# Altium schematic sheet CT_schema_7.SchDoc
size 370 x 335 mm
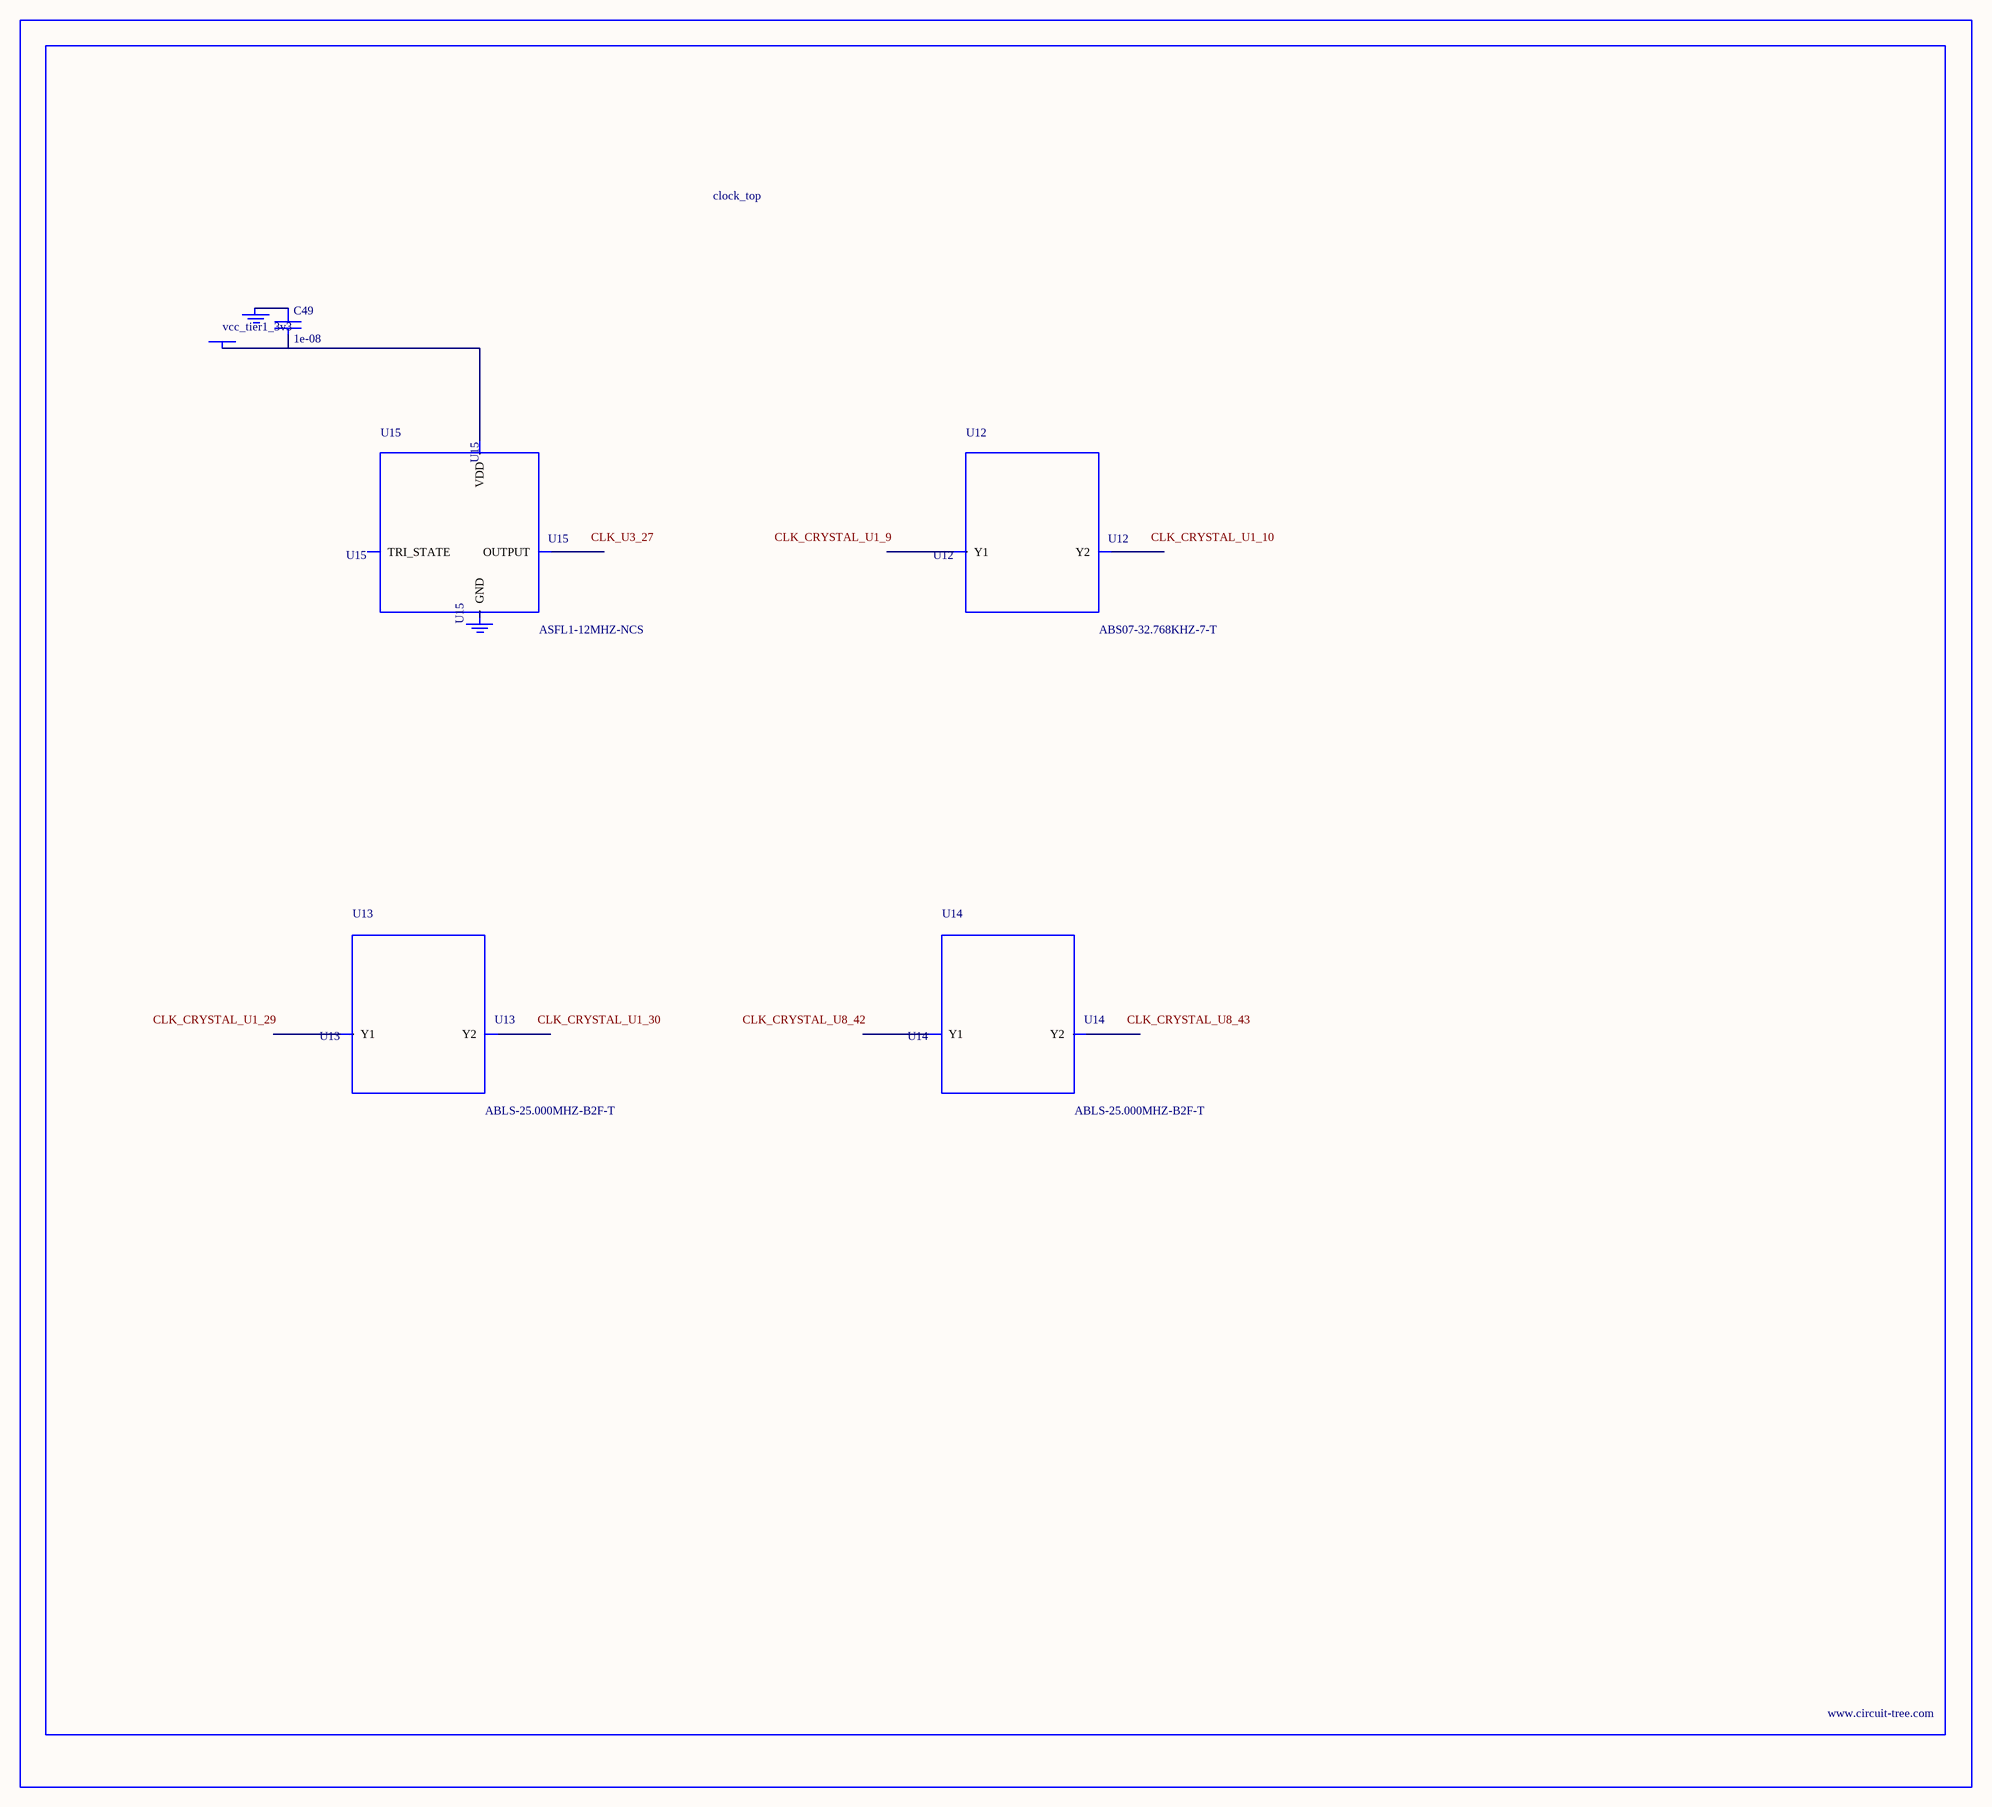
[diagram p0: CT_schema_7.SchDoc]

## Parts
BORDER6  (no value)
C49  1e-08  [C0402]
GND_INSTANCE_6_0  (no value)
GND_INSTANCE_6_1  (no value)
POWER_INSTANCE_6_0  vcc_tier1_3v3
U12  ABS07-32.768KHZ-7-T  [ABS07-32.768KHZ-7-T]
U13  ABLS-25.000MHZ-B2F-T  [ABLS-25.000MHZ-B2F-T]
U14  ABLS-25.000MHZ-B2F-T  [ABLS-25.000MHZ-B2F-T]
U15  ASFL1-12MHZ-NCS  [ASFL1]

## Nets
NetC49_1: C49.1 GND_INSTANCE_6_0.0(GND)
NetC49_2: C49.2 POWER_INSTANCE_6_0.0(PWR) U15.4(VDD)

Not connected (* = marked no-connect by the designer): GND_INSTANCE_6_1 0(GND); U12 1(Y1) 2(Y2); U13 1(Y1) 2(Y2); U14 1(Y1) 2(Y2); U15 1(TRI_STATE) 2(GND) 3(OUTPUT)

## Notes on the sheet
- Labels drawn without touching a wire or pin: CLK_CRYSTAL_U1_9, CLK_CRYSTAL_U1_10, CLK_CRYSTAL_U1_29, CLK_CRYSTAL_U1_30, CLK_CRYSTAL_U8_42, CLK_CRYSTAL_U8_43, CLK_U3_27

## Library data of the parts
BORDER6 = BORDER_PAGE6
C49 = C0402C103K3RAC
GND_INSTANCE_6_0 GND_INSTANCE_6_1 = GND
POWER_INSTANCE_6_0 = PWR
